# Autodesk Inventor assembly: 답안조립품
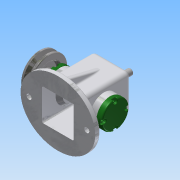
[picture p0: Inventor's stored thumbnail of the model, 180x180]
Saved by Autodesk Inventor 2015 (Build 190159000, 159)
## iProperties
Created: 2017-07
Part Number: 답안조립품
Document SubType Name: Assembly
Designer: Administrator
Author: Administrator
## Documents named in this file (14)
- C:\Users\Administrator\Desktop\470707V1007\답안조립품.iam
- C:\Users\Administrator\Desktop\470707V1007\본체.ipt
- C:\Users\Administrator\Desktop\470707V1007\뒤커버.ipt
- C:\Users\Administrator\Desktop\470707V1007\베어링 12 x 32 x 10.ipt
- C:\Users\Administrator\Desktop\470707V1007\편심축.ipt
- C:\Users\Administrator\Desktop\470707V1007\링크.ipt
- C:\Users\Administrator\Desktop\470707V1007\슬라이드.ipt
- C:\Users\Administrator\Desktop\470707V1007\핀 5 x 18.ipt
- C:\Users\Administrator\Desktop\470707V1007\고정핀 1.2 x  8.ipt
- C:\Users\Administrator\Desktop\470707V1007\앞커버.ipt
- C:\Users\Administrator\Desktop\470707V1007\오일실 12 25 7.ipt
- C:\Users\Administrator\Desktop\470707V1007\부시.ipt
- C:\Users\Administrator\Desktop\470707V1007\V벨트풀리.ipt
- C:\Users\Administrator\Desktop\470707V1007\키 4 x 4 x 10.ipt
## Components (3 placed, 3 different names)
1. 핀 5 x 18:1
2. 고정핀 1.2 x  8:1
3. V벨트풀리:1 — 각도:2
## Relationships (1: Angle 1)
- 각도:2 [Angle]: V벨트풀리:1
